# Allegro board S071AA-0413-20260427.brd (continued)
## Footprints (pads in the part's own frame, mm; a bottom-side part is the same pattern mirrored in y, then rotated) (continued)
SO8_215X127MM
  rect 1.778x0.762 smd: 1(-2.731,2.032) 4(-2.731,-2.032) 5(2.731,-2.032) 8(2.731,2.032)
  rect 1.778x0.61 smd: 2(-2.731,0.635) 3(-2.731,-0.635) 6(2.731,-0.635) 7(2.731,0.635)
SOCKET_CODE
  round 0.051 smd: 1(0,0)
TP_040_T
  round 1.016 smd: 1(0,0)
TP_060_040
  round 1.524 hole 1.016: 1(0,0)
V93K_TOUCHSENSOR_FY
  round 0.051 smd: 1(0,0)

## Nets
AGND: BDB4.1 BDB5.1 BDB6.1 BDB7.1 BDB8.1 BDB9.1 BDB10.1 BDB13.1 BDB14.1 BDB15.1 BDB16.1 BDB17.1 BDB18.1 BDB19.1 BDB20.1 BDB21.1 BDB22.1 BDB23.1 BDB24.1 BDB25.1 BDB26.1 BDB27.1 BDB28.1 BDB29.1 BDB30.1 BDB31.1 BDB32.1 BDB33.1 BDB34.1 BDB35.1 BDB36.1 BDB37.1 BDB38.1 BDB39.1 BDB40.1 BDB41.1 BDB42.1 BDB43.1 BDB44.1 BDB45.1 C1.2 C3.2 C4.2 C5.2 C6.2 C7.2 C8.2 C9.2 C20.2 C21.2 C22.2 C23.2 C24.2 C25.2 C26.2 C27.2 C28.2 C29.2 C30.2 C31.2 C32.2 C33.2 C34.2 C35.2 C36.2 C37.2 C38.2 C39.2 C40.2 C41.2 C42.2 C43.2 C44.2 C45.2 C46.2 C47.2 C48.2 C49.2 C74.2 C75.2 C76.2 C77.2 C78.2 C79.2 C80.2 C81.2 C82.2 C83.2 C84.2 C85.2 CSDPS225.B2 CSDPS225.B4 CSDPS225.B6 CSDPS225.B8 CSDPS225.B10 CSDPS225.B12 CSDPS225.B14 CSDPS225.B16 CSDPS225.C1 CSDPS225.C3 CSDPS225.C5 CSDPS225.C7 CSDPS225.C9 CSDPS225.C11 CSDPS225.C13 CSDPS225.C15 CSDPS226.B2 CSDPS226.B4 CSDPS226.B6 CSDPS226.B8 CSDPS226.B10 CSDPS226.B12 CSDPS226.B14 CSDPS226.B16 CSDPS226.C1 CSDPS226.C3 CSDPS226.C5 CSDPS226.C7 CSDPS226.C9 CSDPS226.C11 CSDPS226.C13 CSDPS226.C15 CSDPS229.B2 CSDPS229.B4 CSDPS229.B6 CSDPS229.B8 CSDPS229.B10 CSDPS229.B12 CSDPS229.B14 CSDPS229.B16 CSDPS229.C1 CSDPS229.C3 CSDPS229.C5 CSDPS229.C7 CSDPS229.C9 CSDPS229.C11 CSDPS229.C13 CSDPS229.C15 CSDPS425.B2 CSDPS425.B4 CSDPS425.B6 CSDPS425.B8 CSDPS425.B10 CSDPS425.B12 CSDPS425.B14 CSDPS425.B16 CSDPS425.C1 CSDPS425.C3 CSDPS425.C5 CSDPS425.C7 CSDPS425.C9 CSDPS425.C11 CSDPS425.C13 CSDPS425.C15 CSDPS426.B2 CSDPS426.B4 CSDPS426.B6 CSDPS426.B8 CSDPS426.B10 CSDPS426.B12 CSDPS426.B14 CSDPS426.B16 CSDPS426.C1 CSDPS426.C3 CSDPS426.C5 CSDPS426.C7 CSDPS426.C9 CSDPS426.C11 CSDPS426.C13 CSDPS426.C15 CSDPS429.B2 CSDPS429.B4 CSDPS429.B6 CSDPS429.B8 CSDPS429.B10 CSDPS429.B12 CSDPS429.B14 CSDPS429.B16 CSDPS429.C1 CSDPS429.C3 CSDPS429.C5 CSDPS429.C7 CSDPS429.C9 CSDPS429.C11 CSDPS429.C13 CSDPS429.C15 D101.A1 D101.A2 D101.A3 D101.A4 D101.A5 D101.A6 D101.A7 D101.A8 D101.A9 D101.A10 D101.A11 D101.A12 D101.A13 D101.A14 D101.A15 D101.A16 D101.B1 D101.B2 D101.B3 D101.B4 D101.B5 D101.B6 D101.B7 D101.B8 D101.B9 D101.B10 D101.B11 D101.B12 D101.B13 D101.B14 D101.B15 D101.B16 D102.A1 D102.A2 D102.A3 D102.A4 D102.A5 D102.A6 D102.A7 D102.A8 D102.A9 D102.A10 D102.A11 D102.A12 D102.A13 D102.A14 D102.A15 D102.A16 D102.B1 D102.B2 D102.B3 D102.B4 D102.B5 D102.B6 D102.B7 D102.B8 D102.B9 D102.B10 D102.B11 D102.B12 D102.B13 D102.B14 D102.B15 D102.B16 D103.A1 D103.A2 D103.A3 D103.A4 D103.A5 D103.A6 D103.A7 D103.A8 D103.A9 D103.A10 D103.A11 D103.A12 D103.A13 D103.A14 D103.A15 D103.A16 D103.B1 D103.B2 D103.B3 D103.B4 D103.B5 D103.B6 D103.B7 D103.B8 D103.B9 D103.B10 D103.B11 D103.B12 D103.B13 D103.B14 D103.B15 D103.B16 D104.A1 D104.A2 D104.A3 D104.A4 D104.A5 D104.A6 D104.A7 D104.A8 D104.A9 D104.A10 D104.A11 D104.A12 D104.A13 D104.A14 D104.A15 D104.A16 D104.B1 D104.B2 D104.B3 D104.B4 D104.B5 D104.B6 D104.B7 D104.B8 D104.B9 D104.B10 D104.B11 D104.B12 D104.B13 D104.B14 D104.B15 D104.B16 D105.A1 D105.A2 D105.A3 D105.A4 D105.A5 D105.A6 D105.A7 D105.A8 D105.A9 D105.A10 D105.A11 D105.A12 D105.A13 D105.A14 D105.A15 D105.A16 D105.B1 D105.B2 D105.B3 D105.B4 D105.B5 D105.B6 D105.B7 D105.B8 D105.B9 D105.B10 D105.B11 D105.B12 D105.B13 D105.B14 D105.B15 D105.B16 D106.A1 D106.A2 D106.A3 D106.A4 D106.A5 D106.A6 D106.A7 D106.A8 D106.A9 D106.A10 D106.A11 D106.A12 D106.A13 D106.A14 D106.A15 D106.A16 D106.B1 D106.B2 D106.B3 D106.B4 D106.B5 D106.B6 D106.B7 D106.B8 D106.B9 D106.B10 D106.B11 D106.B12 D106.B13 D106.B14 D106.B15 D106.B16 D107.A1 D107.A2 D107.A3 D107.A4 D107.A5 D107.A6 D107.A7 D107.A8 D107.A9 D107.A10 D107.A11 D107.A12 D107.A13 D107.A14 D107.A15 D107.A16 D107.B1 D107.B2 D107.B3 D107.B4 D107.B5 D107.B6 D107.B7 D107.B8 D107.B9 D107.B10 D107.B11 D107.B12 D107.B13 D107.B14 D107.B15 D107.B16 D108.A1 D108.A2 D108.A3 D108.A4 D108.A5 D108.A6 D108.A7 D108.A8 D108.A9 D108.A10 D108.A11 D108.A12 D108.A13 D108.A14 D108.A15 D108.A16 D108.B1 D108.B2 D108.B3 D108.B4 D108.B5 D108.B6 D108.B7 D108.B8 D108.B9 D108.B10 D108.B11 D108.B12 D108.B13 D108.B14 D108.B15 D108.B16 D109.A1 D109.A2 D109.A3 D109.A4 D109.A5 D109.A6 D109.A7 D109.A8 D109.A9 D109.A10 D109.A11 D109.A12 D109.A13 D109.A14 D109.A15 D109.A16 D109.B1 D109.B2 D109.B3 D109.B4 D109.B5 D109.B6 D109.B7 D109.B8 D109.B9 D109.B10 D109.B11 D109.B12 D109.B13 D109.B14 D109.B15 D109.B16 D110.A1 D110.A2 D110.A3 D110.A4 D110.A5 D110.A6 D110.A7 D110.A8 D110.A9 D110.A10 D110.A11 D110.A12 D110.A13 D110.A14 D110.A15 D110.A16 D110.B1 D110.B2 D110.B3 D110.B4 D110.B5 D110.B6 D110.B7 D110.B8 D110.B9 D110.B10 D110.B11 D110.B12 D110.B13 D110.B14 D110.B15 D110.B16 D111.A1 D111.A2 D111.A3 D111.A4 D111.A5 D111.A6 D111.A7 D111.A8 D111.A9 D111.A10 D111.A11 D111.A12 D111.A13 D111.A14 D111.A15 D111.A16 D111.B1 D111.B2 D111.B3 D111.B4 D111.B5 D111.B6 D111.B7 D111.B8 D111.B9 D111.B10 D111.B11 D111.B12 D111.B13 D111.B14 D111.B15 D111.B16 D112.A1 D112.A2 D112.A3 D112.A4 D112.A5 D112.A6 D112.A7 D112.A8 D112.A9 D112.A10 D112.A11 D112.A12 D112.A13 D112.A14 D112.A15 D112.A16 D112.B1 D112.B2 D112.B3 D112.B4 D112.B5 D112.B6 D112.B7 D112.B8 D112.B9 D112.B10 D112.B11 D112.B12 D112.B13 D112.B14 D112.B15 D112.B16 D113.A1 D113.A2 D113.A3 D113.A4 D113.A5 D113.A6 D113.A7 D113.A8 D113.A9 D113.A10 D113.A11 D113.A12 D113.A13 D113.A14 D113.A15 D113.A16 D113.B1 D113.B2 D113.B3 D113.B4 D113.B5 D113.B6 D113.B7 D113.B8 D113.B9 D113.B10 D113.B11 D113.B12 D113.B13 D113.B14 D113.B15 D113.B16 D114.A1 D114.A2 D114.A3 D114.A4 D114.A5 D114.A6 D114.A7 D114.A8 D114.A9 D114.A10 D114.A11 D114.A12 D114.A13 D114.A14 D114.A15 D114.A16 D114.B1 D114.B2 D114.B3 D114.B4 D114.B5 D114.B6 D114.B7 D114.B8 D114.B9 D114.B10 D114.B11 D114.B12 D114.B13 D114.B14 D114.B15 D114.B16 D115.A1 D115.A2 D115.A3 D115.A4 D115.A5 D115.A6 D115.A7 D115.A8 D115.A9 D115.A10 D115.A11 D115.A12 D115.A13 D115.A14 D115.A15 D115.A16 D115.B1 D115.B2 D115.B3 D115.B4 D115.B5 D115.B6 D115.B7 D115.B8 D115.B9 D115.B10 D115.B11 D115.B12 D115.B13 D115.B14 D115.B15 D115.B16 D116.A1 D116.A2 D116.A3 D116.A4 D116.A5 D116.A6 D116.A7 D116.A8 D116.A9 D116.A10 D116.A11 D116.A12 D116.A13 D116.A14 D116.A15 D116.A16 D116.B1 D116.B2 D116.B3 D116.B4 D116.B5 D116.B6 D116.B7 D116.B8 D116.B9 D116.B10 D116.B11 D116.B12 D116.B13 D116.B14 D116.B15 D116.B16 D117.A1 D117.A2 D117.A3 D117.A4 D117.A5 D117.A6 D117.A7 D117.A8 D117.A9 D117.A10 D117.A11 D117.A12 D117.A13 D117.A14 D117.A15 D117.A16 D117.B1 D117.B2 D117.B3 D117.B4 D117.B5 D117.B6 D117.B7 D117.B8 D117.B9 D117.B10 D117.B11 D117.B12 D117.B13 D117.B14 D117.B15 D117.B16 D118.A1 D118.A2 D118.A3 D118.A4 D118.A5 D118.A6 D118.A7 D118.A8 D118.A9 D118.A10 D118.A11 D118.A12 D118.A13 D118.A14 D118.A15 D118.A16 D118.B1 D118.B2 D118.B3 D118.B4 D118.B5 D118.B6 D118.B7 D118.B8 D118.B9 D118.B10 D118.B11 D118.B12 D118.B13 D118.B14 D118.B15 D118.B16 D119.A1 D119.A2 D119.A3 D119.A4 D119.A5 D119.A6 D119.A7 D119.A8 D119.A9 D119.A10 D119.A11 D119.A12 D119.A13 D119.A14 D119.A15 D119.A16 D119.B1 D119.B2 D119.B3 D119.B4 D119.B5 D119.B6 D119.B7 D119.B8 D119.B9 D119.B10 D119.B11 D119.B12 D119.B13 D119.B14 D119.B15 D119.B16 D120.A1 D120.A2 D120.A3 D120.A4 D120.A5 D120.A6 D120.A7 D120.A8 D120.A9 D120.A10 D120.A11 D120.A12 D120.A13 D120.A14 D120.A15 D120.A16 D120.B1 D120.B2 D120.B3 D120.B4 D120.B5 D120.B6 D120.B7 D120.B8 D120.B9 D120.B10 D120.B11 D120.B12 D120.B13 D120.B14 D120.B15 D120.B16 D121.A1 D121.A2 D121.A3 D121.A4 D121.A5 D121.A6 D121.A7 D121.A8 D121.A9 D121.A10 D121.A11 D121.A12 D121.A13 D121.A14 D121.A15 D121.A16 D121.B1 D121.B2 D121.B3 D121.B4 D121.B5 D121.B6 D121.B7 D121.B8 D121.B9 D121.B10 D121.B11 D121.B12 D121.B13 D121.B14 D121.B15 D121.B16 D122.A1 D122.A2 D122.A3 D122.A4 D122.A5 D122.A6 D122.A7 D122.A8 D122.A9 D122.A10 D122.A11 D122.A12 D122.A13 D122.A14 D122.A15 D122.A16 D122.B1 D122.B2 D122.B3 D122.B4 D122.B5 D122.B6 D122.B7 D122.B8 D122.B9 D122.B10 D122.B11 D122.B12 D122.B13 D122.B14 D122.B15 D122.B16 D123.A1 D123.A2 D123.A3 D123.A4 D123.A5 D123.A6 D123.A7 D123.A8 D123.A9 D123.A10 D123.A11 D123.A12 D123.A13 D123.A14 D123.A15 D123.A16 D123.B1 D123.B2 D123.B3 D123.B4 D123.B5 D123.B6 D123.B7 D123.B8 D123.B9 D123.B10 D123.B11 D123.B12 D123.B13 D123.B14 D123.B15 D123.B16 D124.A1 D124.A2 D124.A3 D124.A4 D124.A5 D124.A6 D124.A7 D124.A8 D124.A9 D124.A10 D124.A11 D124.A12 D124.A13 D124.A14 D124.A15 D124.A16 D124.B1 D124.B2 D124.B3 D124.B4 D124.B5 D124.B6 D124.B7 D124.B8 D124.B9 D124.B10 D124.B11 D124.B12 D124.B13 D124.B14 D124.B15 D124.B16 D227.A1 D227.A2 D227.A3 D227.A4 D227.A5 D227.A6 D227.A7 D227.A8 D227.A9 D227.A10 D227.A11 D227.A12 D227.A13 D227.A14 D227.A15 D227.A16 D227.A17 D227.B1 D227.B2 D227.B3 D227.B4 D227.B5 D227.B6 D227.B7 D227.B8 D227.B9 D227.B10 D227.B11 D227.B12 D227.B13 D227.B14 D227.B15 D227.B16 D227.B17 D228.A1 D228.A2 D228.A3 D228.A4 D228.A5 D228.A6 D228.A7 D228.A8 D228.A9 D228.A10 D228.A11 D228.A12 D228.A13 D228.A14 D228.A15 D228.A16 D228.A17 D228.B1 D228.B2 D228.B3 D228.B4 D228.B5 D228.B6 D228.B7 D228.B8 D228.B9 D228.B10 D228.B11 D228.B12 D228.B13 D228.B14 D228.B15 D228.B16 D228.B17 D231.A1 D231.A2 D231.A3 D231.A4 D231.A5 D231.A6 D231.A7 D231.A8 D231.A9 D231.A10 D231.A11 D231.A12 D231.A13 D231.A14 D231.A15 D231.A16 D231.A17 D231.B1 D231.B2 D231.B3 D231.B4 D231.B5 D231.B6 D231.B7 D231.B8 D231.B9 D231.B10 D231.B11 D231.B12 D231.B13 D231.B14 D231.B15 D231.B16 D231.B17 D232.A1 D232.A2 D232.A3 D232.A4 D232.A5 D232.A6 D232.A7 D232.A8 D232.A9 D232.A10 D232.A11 D232.A12 D232.A13 D232.A14 D232.A15 D232.A16 D232.A17 D232.B1 D232.B2 D232.B3 D232.B4 D232.B5 D232.B6 D232.B7 D232.B8 D232.B9 D232.B10 D232.B11 D232.B12 D232.B13 D232.B14 D232.B15 D232.B16 D232.B17 D427.A1 D427.A2 D427.A3 D427.A4 D427.A5 D427.A6 D427.A7 D427.A8 D427.A9 D427.A10 D427.A11 D427.A12 D427.A13 D427.A14 D427.A15 D427.A16 D427.A17 D427.B1 D427.B2 D427.B3 D427.B4 D427.B5 D427.B6 D427.B7 D427.B8 D427.B9 D427.B10 D427.B11 D427.B12 D427.B13 D427.B14 D427.B15 D427.B16 D427.B17 D428.A1 D428.A2 D428.A3 D428.A4 D428.A5 D428.A6 D428.A7 D428.A8 D428.A9 D428.A10 D428.A11 D428.A12 D428.A13 D428.A14 D428.A15 D428.A16 D428.A17 D428.B1 D428.B2 D428.B3 D428.B4 D428.B5 D428.B6 D428.B7 D428.B8 D428.B9 D428.B10 D428.B11 D428.B12 D428.B13 D428.B14 D428.B15 D428.B16 D428.B17 D431.A1 D431.A2 D431.A3 D431.A4 D431.A5 D431.A6 D431.A7 D431.A8 D431.A9 D431.A10 D431.A11 D431.A12 D431.A13 D431.A14 D431.A15 D431.A16 D431.A17 D431.B1 D431.B2 D431.B3 D431.B4 D431.B5 D431.B6 D431.B7 D431.B8 D431.B9 D431.B10 D431.B11 D431.B12 D431.B13 D431.B14 D431.B15 D431.B16 D431.B17 D432.A1 D432.A2 D432.A3 D432.A4 D432.A5 D432.A6 D432.A7 D432.A8 D432.A9 D432.A10 D432.A11 D432.A12 D432.A13 D432.A14 D432.A15 D432.A16 D432.A17 D432.B1 D432.B2 D432.B3 D432.B4 D432.B5 D432.B6 D432.B7 D432.B8 D432.B9 D432.B10 D432.B11 D432.B12 D432.B13 D432.B14 D432.B15 D432.B16 D432.B17 DPS1.A01 DPS1.A05 DPS1.A11 DPS1.A15 DPS1.B01 DPS1.B05 DPS1.B11 DPS1.B15 DPS1.C01 DPS1.C05 DPS1.C11 DPS1.C15 DPS2.A01 DPS2.A05 DPS2.A11 DPS2.A15 DPS2.B01 DPS2.B05 DPS2.B11 DPS2.B15 DPS2.C01 DPS2.C05 DPS2.C11 DPS2.C15 DPS3.A01 DPS3.A05 DPS3.A11 DPS3.A15 DPS3.B01 DPS3.B05 DPS3.B11 DPS3.B15 DPS3.C01 DPS3.C05 DPS3.C11 DPS3.C15 DPS8.A01 DPS8.A05 DPS8.A11 DPS8.A15 DPS8.B01 DPS8.B05 DPS8.B11 DPS8.B15 DPS8.C01 DPS8.C05 DPS8.C11 DPS8.C15 KS3.6(GND2) KS3.7(GND1) KS4.6(GND2) KS4.7(GND1) OSC1.2(GND) SB1.1 SB13.1 SB14.1 SB15.1 SH4.1 SH14.1 SH16.1 SITE1.E5(GNDK[1]) SITE1.E6(GNDK[2]) SITE1.E9(GNDK[3]) SITE1.E13(GNDK[4]) SITE1.E14(GNDK[5]) SITE1.F16(GNDK[6]) SITE1.G16(GNDK[7]) SITE1.H5(GNDK[8]) SITE1.H10(GNDK[9]) SITE1.H11(GNDK[10]) SITE1.J5(GNDK[11]) SITE1.J10(GNDK[12]) SITE1.J11(GNDK[13]) SITE1.K8(GNDK[14]) SITE1.K9(GNDK[15]) SITE1.K10(GNDK[16]) SITE1.K11(GNDK[17]) SITE1.K12(GNDK[18]) SITE1.K13(GNDK[19]) SITE1.L8(GNDK[20]) SITE1.L9(GNDK[21]) SITE1.L10(GNDK[22]) SITE1.L11(GNDK[23]) SITE1.L12(GNDK[24]) SITE1.M3(GNDK[25]) SITE1.M4(GNDK[26]) SITE1.M5(GNDK[27]) SITE1.M10(GNDK[28]) SITE1.M11(GNDK[29]) SITE1.T11(GND3IO_OSC) SITE1.T15(GNDK[30]) UHC230.G3 UHC230.G3_1 UHC230.G3_2 UHC230.G3_3 UHC230.G3_4 UHC230.G3_5 UHC230.G3_6 UHC230.G3_7 UHC230.G3_8 UHC230.G3_9 UHC230.G3_10 UHC230.G3_11 UHC230.G3_12 UHC230.G3_13 UHC230.G4 UHC230.G4_1 UHC230.G4_2 UHC230.G4_3 UHC230.G4_4 UHC230.G4_5 UHC230.G4_6 UHC230.G4_7 UHC230.G4_8 UHC230.G4_9 UHC230.G4_10 UHC230.G4_11 UHC230.G4_12 UHC230.G4_13 UHC430.G1 UHC430.G1_1 UHC430.G1_2 UHC430.G1_3 UHC430.G1_4 UHC430.G1_5 UHC430.G1_6 UHC430.G1_7 UHC430.G1_8 UHC430.G1_9 UHC430.G1_10 UHC430.G1_11 UHC430.G1_12 UHC430.G1_13 UHC430.G2 UHC430.G2_1 UHC430.G2_2 UHC430.G2_3 UHC430.G2_4 UHC430.G2_5 UHC430.G2_6 UHC430.G2_7 UHC430.G2_8 UHC430.G2_9 UHC430.G2_10 UHC430.G2_11 UHC430.G2_12 UHC430.G2_13
GND12A_SCG: BDB5.2 BDB6.2 BDB7.2 BDB8.2 BDB38.2 BDB39.2 BDB40.2 BDB41.2 C10.2 C50.2 C51.2 C52.2 C53.2 C54.2 C55.2 SH6.1 SITE1.T14(GND12A_SCG)
GND33A_ADC12: BDB9.2 BDB10.2 BDB17.2 BDB18.2 BDB34.2 BDB35.2 BDB36.2 BDB37.2 C11.2 C12.2 C13.2 C14.2 C56.2 C57.2 C58.2 C59.2 C60.2 C61.2 K33.6(GND2) K33.7(GND1) K34.6(GND2) K34.7(GND1) K35.6(GND2) K35.7(GND1) K36.6(GND2) K36.7(GND1) K37.6(GND2) K37.7(GND1) K38.6(GND2) K38.7(GND1) K39.6(GND2) K39.7(GND1) K40.6(GND2) K40.7(GND1) K41.6(GND2) K41.7(GND1) K42.6(GND2) K42.7(GND1) K43.6(GND2) K43.7(GND1) K44.6(GND2) K44.7(GND1) SH8.1 SITE1.N11(GND33D_ADC12) SITE1.T7(GND33A_ADC12[1]) SITE1.T10(XVRB_ADC12) SITE1.U10(GND33A_ADC12[2]) SITE1.V10(GND33A_ADC12[3]) SITE1.W6(GND33A_ADC12[4]) SITE1.W10(GND33A_ADC12[5]) SITE1.Y6(GND33A_ADC12[6]) SITE1.Y10(GND33A_ADC12[7])
GND33A_ADC32: BDB13.2 BDB14.2 BDB15.2 BDB16.2 BDB30.2 BDB31.2 BDB32.2 BDB33.2 C15.2 C16.2 C17.2 C18.2 C62.2 C63.2 C64.2 C65.2 C66.2 C67.2 K1.6(GND2) K1.7(GND1) K2.6(GND2) K2.7(GND1) K3.6(GND2) K3.7(GND1) K4.6(GND2) K4.7(GND1) K5.6(GND2) K5.7(GND1) K6.6(GND2) K6.7(GND1) K7.6(GND2) K7.7(GND1) K8.6(GND2) K8.7(GND1) K9.6(GND2) K9.7(GND1) K10.6(GND2) K10.7(GND1) K11.6(GND2) K11.7(GND1) K12.6(GND2) K12.7(GND1) K13.6(GND2) K13.7(GND1) K14.6(GND2) K14.7(GND1) K15.6(GND2) K15.7(GND1) K16.6(GND2) K16.7(GND1) K17.6(GND2) K17.7(GND1) K18.6(GND2) K18.7(GND1) K19.6(GND2) K19.7(GND1) K20.6(GND2) K20.7(GND1) K21.6(GND2) K21.7(GND1) K22.6(GND2) K22.7(GND1) K23.6(GND2) K23.7(GND1) K24.6(GND2) K24.7(GND1) K25.6(GND2) K25.7(GND1) K26.6(GND2) K26.7(GND1) K27.6(GND2) K27.7(GND1) K28.6(GND2) K28.7(GND1) K29.6(GND2) K29.7(GND1) K30.6(GND2) K30.7(GND1) K31.6(GND2) K31.7(GND1) K32.6(GND2) K32.7(GND1) SH10.1 SITE1.N1(GND33A_ADC32[1]) SITE1.N2(GND33A_ADC32[2]) SITE1.N3(GND33A_ADC32[3]) SITE1.N4(GND33A_ADC32[4]) SITE1.N5(GND33A_ADC32[5]) SITE1.N10(GND33D_ADC32) SITE1.P5(GND33A_ADC32[6]) SITE1.T6(XVRB_ADC32) SITE1.U6(GND33A_ADC32[7]) SITE1.V6(GND33A_ADC32[8])
GNDA_REG: BDB22.2 BDB23.2 BDB24.2 BDB25.2 BDB26.2 BDB27.2 BDB28.2 BDB29.2 C2.2 C19.2 C68.2 C69.2 C70.2 C71.2 C72.2 C73.2 SH12.1 SITE1.L13(GNDA_REG)
CSDPS225GS1: CSDPS225.D2
CSDPS225GS2: CSDPS225.A1
CSDPS225GS3: CSDPS225.D4
CSDPS225GS4: CSDPS225.A3
CSDPS225GS5: CSDPS225.D6
CSDPS225GS6: CSDPS225.A5
CSDPS225GS7: CSDPS225.D8
CSDPS225GS8: CSDPS225.A7
CSDPS225GS9: CSDPS225.D10
CSDPS225GS10: CSDPS225.A9
CSDPS225GS11: CSDPS225.D12
CSDPS225GS12: CSDPS225.A11
CSDPS225GS13: CSDPS225.D14
CSDPS225GS14: CSDPS225.A13
CSDPS225GS15: CSDPS225.D16
CSDPS225GS16: CSDPS225.A15
CSDPS225P1: CSDPS225.B1
CSDPS225P2: CSDPS225.C2
CSDPS225P3: CSDPS225.B3
CSDPS225P4: CSDPS225.C4
CSDPS225P5: CSDPS225.B5
CSDPS225P6: CSDPS225.C6
CSDPS225P7: CSDPS225.B7
CSDPS225P8: CSDPS225.C8
CSDPS225P9: CSDPS225.B9
CSDPS225P10: CSDPS225.C10
CSDPS225P11: CSDPS225.B11
CSDPS225P12: CSDPS225.C12
CSDPS225P13: CSDPS225.B13
CSDPS225P14: CSDPS225.C14
CSDPS225P15: CSDPS225.B15
CSDPS225P16: CSDPS225.C16
CSDPS225PS1: CSDPS225.D1
CSDPS225PS2: CSDPS225.A2
CSDPS225PS3: CSDPS225.D3
CSDPS225PS4: CSDPS225.A4
CSDPS225PS5: CSDPS225.D5
CSDPS225PS6: CSDPS225.A6
CSDPS225PS7: CSDPS225.D7
CSDPS225PS8: CSDPS225.A8
CSDPS225PS9: CSDPS225.D9
CSDPS225PS10: CSDPS225.A10
CSDPS225PS11: CSDPS225.D11
CSDPS225PS12: CSDPS225.A12
CSDPS225PS13: CSDPS225.D13
CSDPS225PS14: CSDPS225.A14
CSDPS225PS15: CSDPS225.D15
CSDPS225PS16: CSDPS225.A16
CSDPS226GS1: CSDPS226.D2
CSDPS226GS2: CSDPS226.A1
CSDPS226GS3: CSDPS226.D4
CSDPS226GS4: CSDPS226.A3
CSDPS226GS5: CSDPS226.D6
CSDPS226GS6: CSDPS226.A5
CSDPS226GS7: CSDPS226.D8
CSDPS226GS8: CSDPS226.A7
CSDPS226GS9: CSDPS226.D10
CSDPS226GS10: CSDPS226.A9
CSDPS226GS11: CSDPS226.D12
CSDPS226GS12: CSDPS226.A11
CSDPS226GS13: CSDPS226.D14
CSDPS226GS14: CSDPS226.A13
CSDPS226GS15: CSDPS226.D16
CSDPS226GS16: CSDPS226.A15
CSDPS226P1: CSDPS226.B1
CSDPS226P2: CSDPS226.C2
CSDPS226P3: CSDPS226.B3
CSDPS226P4: CSDPS226.C4
CSDPS226P5: CSDPS226.B5
CSDPS226P6: CSDPS226.C6
CSDPS226P7: CSDPS226.B7
CSDPS226P8: CSDPS226.C8
CSDPS226P9: CSDPS226.B9
CSDPS226P10: CSDPS226.C10
CSDPS226P11: CSDPS226.B11
CSDPS226P12: CSDPS226.C12
CSDPS226P13: CSDPS226.B13
CSDPS226P14: CSDPS226.C14
CSDPS226P15: CSDPS226.B15
CSDPS226P16: CSDPS226.C16
CSDPS226PS1: CSDPS226.D1
CSDPS226PS2: CSDPS226.A2
CSDPS226PS3: CSDPS226.D3
CSDPS226PS4: CSDPS226.A4
CSDPS226PS5: CSDPS226.D5
CSDPS226PS6: CSDPS226.A6
CSDPS226PS7: CSDPS226.D7
CSDPS226PS8: CSDPS226.A8
CSDPS226PS9: CSDPS226.D9
CSDPS226PS10: CSDPS226.A10
CSDPS226PS11: CSDPS226.D11
CSDPS226PS12: CSDPS226.A12
CSDPS226PS13: CSDPS226.D13
CSDPS226PS14: CSDPS226.A14
CSDPS226PS15: CSDPS226.D15
CSDPS226PS16: CSDPS226.A16
CSDPS226WW: CSDPS226.B17
CSDPS226XX: CSDPS226.C17
CSDPS229GS1: CSDPS229.D2
CSDPS229GS2: CSDPS229.A1
CSDPS229GS3: CSDPS229.D4
CSDPS229GS4: CSDPS229.A3
CSDPS229GS5: CSDPS229.D6
CSDPS229GS6: CSDPS229.A5
CSDPS229GS7: CSDPS229.D8
CSDPS229GS8: CSDPS229.A7
CSDPS229GS9: CSDPS229.D10
CSDPS229GS10: CSDPS229.A9
CSDPS229GS11: CSDPS229.D12
CSDPS229GS12: CSDPS229.A11
CSDPS229GS13: CSDPS229.D14
CSDPS229GS14: CSDPS229.A13
CSDPS229GS15: CSDPS229.D16
CSDPS229GS16: CSDPS229.A15
CSDPS229P1: CSDPS229.B1
CSDPS229P2: CSDPS229.C2
CSDPS229P3: CSDPS229.B3
CSDPS229P4: CSDPS229.C4
CSDPS229P5: CSDPS229.B5
CSDPS229P6: CSDPS229.C6
CSDPS229P7: CSDPS229.B7
CSDPS229P8: CSDPS229.C8
CSDPS229P9: CSDPS229.B9
CSDPS229P10: CSDPS229.C10
CSDPS229P11: CSDPS229.B11
CSDPS229P12: CSDPS229.C12
CSDPS229P13: CSDPS229.B13
CSDPS229P14: CSDPS229.C14
CSDPS229P15: CSDPS229.B15
CSDPS229P16: CSDPS229.C16
CSDPS229PS1: CSDPS229.D1
CSDPS229PS2: CSDPS229.A2
CSDPS229PS3: CSDPS229.D3
CSDPS229PS4: CSDPS229.A4
CSDPS229PS5: CSDPS229.D5
CSDPS229PS6: CSDPS229.A6
CSDPS229PS7: CSDPS229.D7
CSDPS229PS8: CSDPS229.A8
CSDPS229PS9: CSDPS229.D9
CSDPS229PS10: CSDPS229.A10
CSDPS229PS11: CSDPS229.D11
CSDPS229PS12: CSDPS229.A12
CSDPS229PS13: CSDPS229.D13
CSDPS229PS14: CSDPS229.A14
CSDPS229PS15: CSDPS229.D15
CSDPS229PS16: CSDPS229.A16
CSDPS425GS1: CSDPS425.D2
CSDPS425GS2: CSDPS425.A1
CSDPS425GS3: CSDPS425.D4
CSDPS425GS4: CSDPS425.A3
CSDPS425GS5: CSDPS425.D6
CSDPS425GS6: CSDPS425.A5
CSDPS425GS7: CSDPS425.D8
CSDPS425GS8: CSDPS425.A7
CSDPS425GS9: CSDPS425.D10
CSDPS425GS10: CSDPS425.A9
CSDPS425GS11: CSDPS425.D12
CSDPS425GS12: CSDPS425.A11
CSDPS425GS13: CSDPS425.D14
CSDPS425GS14: CSDPS425.A13
CSDPS425GS15: CSDPS425.D16
CSDPS425GS16: CSDPS425.A15
CSDPS425P1: CSDPS425.B1
CSDPS425P2: CSDPS425.C2
CSDPS425P3: CSDPS425.B3
CSDPS425P4: CSDPS425.C4
CSDPS425P5: CSDPS425.B5
CSDPS425P6: CSDPS425.C6
CSDPS425P7: CSDPS425.B7
CSDPS425P8: CSDPS425.C8
CSDPS425P9: CSDPS425.B9
CSDPS425P10: CSDPS425.C10
CSDPS425P11: CSDPS425.B11
CSDPS425P12: CSDPS425.C12
CSDPS425P13: CSDPS425.B13
CSDPS425P14: CSDPS425.C14
CSDPS425P15: CSDPS425.B15
CSDPS425P16: CSDPS425.C16
CSDPS425PS1: CSDPS425.D1
CSDPS425PS2: CSDPS425.A2
CSDPS425PS3: CSDPS425.D3
CSDPS425PS4: CSDPS425.A4
CSDPS425PS5: CSDPS425.D5
CSDPS425PS6: CSDPS425.A6
CSDPS425PS7: CSDPS425.D7
CSDPS425PS8: CSDPS425.A8
CSDPS425PS9: CSDPS425.D9
CSDPS425PS10: CSDPS425.A10
CSDPS425PS11: CSDPS425.D11
CSDPS425PS12: CSDPS425.A12
CSDPS425PS13: CSDPS425.D13
CSDPS425PS14: CSDPS425.A14
CSDPS425PS15: CSDPS425.D15
CSDPS425PS16: CSDPS425.A16
CSDPS426GS1: CSDPS426.D2
CSDPS426GS2: CSDPS426.A1
CSDPS426GS3: CSDPS426.D4
CSDPS426GS4: CSDPS426.A3
CSDPS426GS5: CSDPS426.D6
CSDPS426GS6: CSDPS426.A5
CSDPS426GS7: CSDPS426.D8
CSDPS426GS8: CSDPS426.A7
CSDPS426GS9: CSDPS426.D10
CSDPS426GS10: CSDPS426.A9
CSDPS426GS11: CSDPS426.D12
CSDPS426GS12: CSDPS426.A11
CSDPS426GS13: CSDPS426.D14
CSDPS426GS14: CSDPS426.A13
CSDPS426GS15: CSDPS426.D16
CSDPS426GS16: CSDPS426.A15
CSDPS426P1: CSDPS426.B1
CSDPS426P2: CSDPS426.C2
CSDPS426P3: CSDPS426.B3
CSDPS426P4: CSDPS426.C4
CSDPS426P5: CSDPS426.B5
CSDPS426P6: CSDPS426.C6
CSDPS426P7: CSDPS426.B7
CSDPS426P8: CSDPS426.C8
CSDPS426P9: CSDPS426.B9
CSDPS426P10: CSDPS426.C10
CSDPS426P11: CSDPS426.B11
CSDPS426P12: CSDPS426.C12
CSDPS426P13: CSDPS426.B13
CSDPS426P14: CSDPS426.C14
CSDPS426P15: CSDPS426.B15
CSDPS426P16: CSDPS426.C16
CSDPS426PS1: CSDPS426.D1
CSDPS426PS2: CSDPS426.A2
CSDPS426PS3: CSDPS426.D3
CSDPS426PS4: CSDPS426.A4
CSDPS426PS5: CSDPS426.D5
CSDPS426PS6: CSDPS426.A6
CSDPS426PS7: CSDPS426.D7
CSDPS426PS8: CSDPS426.A8
CSDPS426PS9: CSDPS426.D9
CSDPS426PS10: CSDPS426.A10
CSDPS426PS11: CSDPS426.D11
CSDPS426PS12: CSDPS426.A12
CSDPS426PS13: CSDPS426.D13
CSDPS426PS14: CSDPS426.A14
CSDPS426PS15: CSDPS426.D15
CSDPS426PS16: CSDPS426.A16
CSDPS426WW: CSDPS426.B17
CSDPS426XX: CSDPS426.C17
CSDPS429GS1: CSDPS429.D2
CSDPS429GS2: CSDPS429.A1
CSDPS429GS3: CSDPS429.D4
CSDPS429GS4: CSDPS429.A3
CSDPS429GS5: CSDPS429.D6
CSDPS429GS6: CSDPS429.A5
CSDPS429GS7: CSDPS429.D8
CSDPS429GS8: CSDPS429.A7
CSDPS429GS9: CSDPS429.D10
CSDPS429GS10: CSDPS429.A9
CSDPS429GS11: CSDPS429.D12
CSDPS429GS12: CSDPS429.A11
CSDPS429GS13: CSDPS429.D14
CSDPS429GS14: CSDPS429.A13
CSDPS429GS15: CSDPS429.D16
CSDPS429GS16: CSDPS429.A15
CSDPS429P1: CSDPS429.B1
CSDPS429P2: CSDPS429.C2
CSDPS429P3: CSDPS429.B3
CSDPS429P4: CSDPS429.C4
CSDPS429P5: CSDPS429.B5
CSDPS429P6: CSDPS429.C6
CSDPS429P7: CSDPS429.B7
CSDPS429P8: CSDPS429.C8
CSDPS429P9: CSDPS429.B9
CSDPS429P10: CSDPS429.C10
CSDPS429P11: CSDPS429.B11
CSDPS429P12: CSDPS429.C12
CSDPS429P13: CSDPS429.B13
CSDPS429P14: CSDPS429.C14
CSDPS429P15: CSDPS429.B15
CSDPS429P16: CSDPS429.C16
CSDPS429PS1: CSDPS429.D1
CSDPS429PS2: CSDPS429.A2
CSDPS429PS3: CSDPS429.D3
CSDPS429PS4: CSDPS429.A4
CSDPS429PS5: CSDPS429.D5
CSDPS429PS6: CSDPS429.A6
CSDPS429PS7: CSDPS429.D7
CSDPS429PS8: CSDPS429.A8
CSDPS429PS9: CSDPS429.D9
CSDPS429PS10: CSDPS429.A10
CSDPS429PS11: CSDPS429.D11
CSDPS429PS12: CSDPS429.A12
CSDPS429PS13: CSDPS429.D13
CSDPS429PS14: CSDPS429.A14
CSDPS429PS15: CSDPS429.D15
CSDPS429PS16: CSDPS429.A16
D227_4_TRIG: D227.04
D228_4_TRIG: D228.04
D231_MCB1_CT2: D231.17 TR3.1
D231_MCB1_E+: D231.16
D231_MCB1_E-: D231.15
D231_MCB1_EE+: D231.08
D231_MCB1_EE-: D231.07
D231_MCB1_F+: D231.14
D231_MCB1_F-: D231.13
D231_MCB1_FF+: D231.06
D231_MCB1_FF-: D231.05
D231_MCB1_G+: D231.12
D231_MCB1_G-: D231.11
D231_MCB1_GG+: D231.04
D231_MCB1_GG-: D231.03
D231_MCB1_H+: D231.10
D231_MCB1_H-: D231.09
D231_MCB1_HH+: D231.02
D231_MCB1_HH-: D231.01
D232_4_TRIG: D232.04
D232_MCB1_CT2: D232.17
D232_MCB1_E+: D232.16
D232_MCB1_E-: D232.15
D232_MCB1_EE+: D232.08
D232_MCB1_EE-: D232.07
D232_MCB1_F+: D232.14
D232_MCB1_F-: D232.13
D232_MCB1_FF+: D232.06
D232_MCB1_FF-: D232.05
D232_MCB1_G+: D232.12
D232_MCB1_G-: D232.11
D232_MCB1_GG-: D232.03
D232_MCB1_H+: D232.10
D232_MCB1_H-: D232.09
D232_MCB1_HH+: D232.02
D232_MCB1_HH-: D232.01
D431_MCB1_A+: D431.16 K1.5 K2.5 K3.5 K4.5 K5.5 K6.5 K7.5 K8.5 K9.5 K10.5 K11.5 K12.5 K13.5 K14.5 K15.5 K16.5
D431_MCB1_A-: D431.15 K17.5 K18.5 K19.5 K20.5 K21.5 K22.5 K23.5 K24.5 K25.5 K26.5 K27.5 K28.5 K29.5 K30.5 K31.5 K32.5
D431_MCB1_AA+: D431.08
D431_MCB1_AA-: D431.07
D431_MCB1_B+: D431.14
D431_MCB1_B-: D431.13
D431_MCB1_BB+: D431.06
D431_MCB1_BB-: D431.05
D431_MCB1_C+: D431.12 K33.5 K34.5 K35.5 K36.5 K37.5 K38.5
D431_MCB1_C-: D431.11 K39.5 K40.5 K41.5 K42.5 K43.5 K44.5
D431_MCB1_CC+: D431.04
D431_MCB1_CC-: D431.03
D431_MCB1_CT1: D431.17 TR2.1
D431_MCB1_D+: D431.10
D431_MCB1_D-: D431.09
D431_MCB1_DD+: D431.02
D431_MCB1_DD-: D431.01
D432_MCB1_A+: D432.16
D432_MCB1_A-: D432.15
D432_MCB1_AA+: D432.08
D432_MCB1_AA-: D432.07
D432_MCB1_B+: D432.14
D432_MCB1_B-: D432.13
D432_MCB1_BB+: D432.06
D432_MCB1_BB-: D432.05
D432_MCB1_C+: D432.12
D432_MCB1_C-: D432.11
D432_MCB1_CC+: D432.04
D432_MCB1_CC-: D432.03
D432_MCB1_CT1: D432.17
D432_MCB1_D+: D432.10
D432_MCB1_D-: D432.09
D432_MCB1_DD+: D432.02
D432_MCB1_DD-: D432.01
D10101: D101.01
D10102: D101.02
D10103: D101.03
D10104: D101.04
D10105: D101.05
D10106: D101.06
D10107: D101.07
D10108: D101.08
D10109: D101.09
D10110: D101.10
D10111: D101.11
D10112: D101.12
D10113: D101.13
D10114: D101.14
D10115: D101.15
D10116: D101.16
D10201: D102.01
D10202: D102.02
D10203: D102.03
D10204: D102.04
D10205: D102.05
D10206: D102.06
D10207: D102.07
D10208: D102.08
D10209: D102.09
D10210: D102.10
D10211: D102.11
D10212: D102.12
D10213: D102.13
D10214: D102.14
D10215: D102.15
D10216: D102.16
D10301: D103.01
D10302: D103.02
D10303: D103.03
D10304: D103.04
D10305: D103.05
D10306: D103.06
D10307: D103.07
D10308: D103.08
D10309: D103.09
D10310: D103.10
D10311: D103.11
D10312: D103.12
D10313: D103.13
D10314: D103.14
D10315: D103.15
D10316: D103.16
D10401: D104.01
D10402: D104.02
D10403: D104.03
D10404: D104.04
D10405: D104.05
D10406: D104.06
D10407: D104.07
D10408: D104.08
D10409: D104.09
D10410: D104.10
D10411: D104.11
D10412: D104.12
D10413: D104.13
D10414: D104.14
D10415: D104.15
D10416: D104.16
D10501: D105.01
D10502: D105.02
D10503: D105.03
D10504: D105.04
D10505: D105.05
D10506: D105.06
D10507: D105.07
D10508: D105.08
D10509: D105.09
D10510: D105.10
D10511: D105.11
D10512: D105.12
D10513: D105.13
D10514: D105.14
D10515: D105.15
D10516: D105.16
D10601: D106.01
D10602: D106.02
D10603: D106.03
D10604: D106.04
D10605: D106.05
D10606: D106.06
D10607: D106.07
D10608: D106.08
D10609: D106.09
D10610: D106.10
D10611: D106.11
D10612: D106.12
D10613: D106.13
D10614: D106.14
D10615: D106.15
D10616: D106.16
D10701: D107.01
D10702: D107.02
D10703: D107.03
D10704: D107.04
D10705: D107.05
D10706: D107.06
D10707: D107.07
D10708: D107.08
D10709: D107.09
D10710: D107.10
D10711: D107.11
D10712: D107.12
D10713: D107.13
D10714: D107.14
D10715: D107.15
D10716: D107.16
D10801: D108.01
D10802: D108.02
D10803: D108.03
D10804: D108.04
D10805: D108.05
D10806: D108.06
D10807: D108.07
D10808: D108.08
D10809: D108.09
D10810: D108.10
D10811: D108.11
D10812: D108.12
D10813: D108.13
D10814: D108.14
D10815: D108.15
D10816: D108.16
D10901: D109.01
D10902: D109.02
D10903: D109.03
D10904: D109.04
D10905: D109.05
D10906: D109.06
D10907: D109.07
D10908: D109.08
D10909: D109.09
D10910: D109.10
D10911: D109.11
D10912: D109.12
D10913: D109.13
D10914: D109.14
D10915: D109.15
D10916: D109.16
D11001: D110.01
D11002: D110.02
D11003: D110.03
D11004: D110.04
D11005: D110.05
D11006: D110.06
D11007: D110.07
D11008: D110.08
D11009: D110.09
D11010: D110.10
D11011: D110.11
D11012: D110.12
D11013: D110.13
D11014: D110.14
D11015: D110.15
D11016: D110.16
D11101: D111.01
D11102: D111.02
D11103: D111.03
D11104: D111.04
D11105: D111.05
D11106: D111.06
D11107: D111.07
D11108: D111.08
D11109: D111.09
D11110: D111.10
D11111: D111.11
D11112: D111.12
D11113: D111.13
D11114: D111.14
D11115: D111.15
D11116: D111.16
D11201: D112.01
D11202: D112.02
D11203: D112.03
D11204: D112.04
D11205: D112.05
D11206: D112.06
D11207: D112.07
D11208: D112.08
D11209: D112.09
D11210: D112.10
D11211: D112.11
D11212: D112.12
D11213: D112.13
D11214: D112.14
D11215: D112.15
D11216: D112.16
D11301: D113.01
D11302: D113.02
D11303: D113.03
D11304: D113.04
D11305: D113.05
D11306: D113.06
D11307: D113.07
D11308: D113.08
D11309: D113.09
D11310: D113.10
D11311: D113.11
D11312: D113.12
D11313: D113.13
D11314: D113.14
D11315: D113.15
D11316: D113.16
D11401: D114.01
D11402: D114.02
D11403: D114.03
D11404: D114.04
D11405: D114.05
D11406: D114.06
D11407: D114.07
D11408: D114.08
D11409: D114.09
D11410: D114.10
D11411: D114.11
D11412: D114.12
D11413: D114.13
D11414: D114.14
D11415: D114.15
D11416: D114.16
D11501: D115.01
D11502: D115.02
D11503: D115.03
D11504: D115.04
D11505: D115.05
D11506: D115.06
D11507: D115.07
D11508: D115.08
D11509: D115.09
D11510: D115.10
D11511: D115.11
D11512: D115.12
D11513: D115.13
D11514: D115.14
D11515: D115.15
D11516: D115.16
D11601: D116.01
D11602: D116.02
D11603: D116.03
D11604: D116.04
D11605: D116.05
D11606: D116.06
D11607: D116.07
D11608: D116.08
D11609: D116.09
D11610: D116.10
D11611: D116.11
D11612: D116.12
D11613: D116.13
D11614: D116.14
D11615: D116.15
D11616: D116.16 TR2.2 TR3.2
D11701: D117.01
D11702: D117.02
D11703: D117.03
D11704: D117.04
D11705: D117.05
D11706: D117.06
D11707: D117.07
D11708: D117.08
D11709: D117.09
D11710: D117.10
D11711: D117.11
D11712: D117.12
D11713: D117.13
D11714: D117.14
D11715: D117.15
D11716: D117.16
D11801: D118.01
D11802: D118.02
D11803: D118.03
D11804: D118.04
D11805: D118.05
D11806: D118.06
D11807: D118.07
D11808: D118.08
D11809: D118.09
D11810: D118.10
D11811: D118.11
D11812: D118.12
D11813: D118.13
D11814: D118.14
D11815: D118.15
D11816: D118.16
D11901: D119.01
D11902: D119.02
D11903: D119.03
D11904: D119.04
D11905: D119.05
D11906: D119.06
D11907: D119.07
D11908: D119.08
D11909: D119.09
D11910: D119.10
D11911: D119.11
D11912: D119.12
D11913: D119.13
D11914: D119.14
D11915: D119.15
D11916: D119.16
D12001: D120.01
D12002: D120.02
D12003: D120.03
D12004: D120.04
D12005: D120.05
D12006: D120.06
D12007: D120.07
D12008: D120.08
D12009: D120.09
D12010: D120.10
D12011: D120.11
D12012: D120.12
D12013: D120.13
D12014: D120.14
D12015: D120.15
D12016: D120.16
D12101: D121.01
D12102: D121.02
D12103: D121.03
D12104: D121.04
D12105: D121.05
D12106: D121.06
D12107: D121.07
D12108: D121.08
D12109: D121.09
D12110: D121.10
D12111: D121.11
D12112: D121.12
D12113: D121.13
D12114: D121.14
D12115: D121.15
D12116: D121.16
D12201: D122.01
D12202: D122.02
D12203: D122.03
D12204: D122.04
D12205: D122.05
D12206: D122.06
D12207: D122.07
D12208: D122.08
D12209: D122.09
D12210: D122.10
D12211: D122.11
D12212: D122.12
D12213: D122.13
D12214: D122.14
D12215: D122.15
D12216: D122.16
D12301: D123.01
D12302: D123.02
D12303: D123.03
D12304: D123.04
D12305: D123.05
D12306: D123.06
D12307: D123.07
D12308: D123.08
D12309: D123.09
D12310: D123.10
D12311: D123.11
D12312: D123.12
D12313: D123.13
D12314: D123.14
D12315: D123.15
D12316: D123.16
D12401: D124.01
D12402: D124.02
D12403: D124.03
D12404: D124.04
D12405: D124.05
D12406: D124.06
D12407: D124.07
D12408: D124.08
D12409: D124.09
D12410: D124.10
D12411: D124.11
D12412: D124.12
D12413: D124.13
D12414: D124.14
D12415: D124.15
D12416: D124.16
GPDPS1_1F: DPS1.A03 DPS1.B03 DPS1.C03 R162.2
GPDPS1_1GRD: DPS1.B02
GPDPS1_1GS: DPS1.A02 R163.2
GPDPS1_1S: DPS1.C02 R160.2
GPDPS1_2F: DPS1.A07 DPS1.B07 DPS1.C07 R155.2
GPDPS1_2GRD: DPS1.B06
GPDPS1_2GS: DPS1.A06 R157.2
GPDPS1_2S: DPS1.C06 R154.2
GPDPS1_3F: DPS1.A13 DPS1.B13 DPS1.C13 R143.2
GPDPS1_3GRD: DPS1.B12
GPDPS1_3GS: DPS1.A12 R145.2
GPDPS1_3S: DPS1.C12 R142.2
GPDPS1_4F: DPS1.A17 DPS1.B17 DPS1.C17 R137.2
GPDPS1_4GRD: DPS1.B16
GPDPS1_4GS: DPS1.A16 R139.2
GPDPS1_4S: DPS1.C16 R136.2
GPDPS1_TR+: DPS1.A09
GPDPS1_TRVB-: DPS1.B09 SB1.2
GPDPS1_VB+: DPS1.C09
GPDPS2_1F: DPS2.A03 DPS2.B03 DPS2.C03 R132.2
GPDPS2_1GRD: DPS2.B02
GPDPS2_1GS: DPS2.A02 R133.2
GPDPS2_1S: DPS2.C02 R130.2
GPDPS2_2F: DPS2.A07 DPS2.B07 DPS2.C07 R149.2
GPDPS2_2GRD: DPS2.B06
GPDPS2_2GS: DPS2.A06 R151.2
GPDPS2_2S: DPS2.C06 R148.2
GPDPS2_3F: DPS2.A13 DPS2.B13 DPS2.C13 R125.2
GPDPS2_3GRD: DPS2.B12
GPDPS2_3GS: DPS2.A12 R127.2
GPDPS2_3S: DPS2.C12 R124.2
GPDPS2_4F: DPS2.A17 DPS2.B17 DPS2.C17
GPDPS2_4GRD: DPS2.B16
GPDPS2_4GS: DPS2.A16
GPDPS2_4S: DPS2.C16
GPDPS2_TR+: DPS2.A09
GPDPS2_TRVB-: DPS2.B09 SB13.2
GPDPS2_VB+: DPS2.C09
GPDPS3_1F: DPS3.A03 DPS3.B03 DPS3.C03
GPDPS3_1GRD: DPS3.B02
GPDPS3_1GS: DPS3.A02
GPDPS3_1S: DPS3.C02
GPDPS3_2F: DPS3.A07 DPS3.B07 DPS3.C07
GPDPS3_2GRD: DPS3.B06
GPDPS3_2GS: DPS3.A06
GPDPS3_2S: DPS3.C06
GPDPS3_3F: DPS3.A13 DPS3.B13 DPS3.C13
GPDPS3_3GRD: DPS3.B12
GPDPS3_3GS: DPS3.A12
GPDPS3_3S: DPS3.C12
GPDPS3_4F: DPS3.A17 DPS3.B17 DPS3.C17
GPDPS3_4GRD: DPS3.B16
GPDPS3_4GS: DPS3.A16
GPDPS3_4S: DPS3.C16
GPDPS3_TR+: DPS3.A09
GPDPS3_TRVB-: DPS3.B09 SB14.2
GPDPS3_VB+: DPS3.C09
GPDPS8_1F: DPS8.A03 DPS8.B03 DPS8.C03
GPDPS8_1GRD: DPS8.B02
GPDPS8_1GS: DPS8.A02
GPDPS8_1S: DPS8.C02
GPDPS8_2F: DPS8.A07 DPS8.B07 DPS8.C07
GPDPS8_2GRD: DPS8.B06
GPDPS8_2GS: DPS8.A06
GPDPS8_2S: DPS8.C06
GPDPS8_3F: DPS8.A13 DPS8.B13 DPS8.C13
GPDPS8_3GRD: DPS8.B12
GPDPS8_3GS: DPS8.A12
GPDPS8_3S: DPS8.C12
GPDPS8_4F: DPS8.A17 DPS8.B17 DPS8.C17
GPDPS8_4GRD: DPS8.B16
GPDPS8_4GS: DPS8.A16
GPDPS8_4S: DPS8.C16
GPDPS8_TR+: DPS8.A09
GPDPS8_TRVB-: DPS8.B09 SB15.2
GPDPS8_VB+: DPS8.C09
S1_ADC1_VIN[0]: K1.8 SITE1.Y5(ADC1_VIN[0])
S1_ADC1_VIN[1]: K2.8 SITE1.W5(ADC1_VIN[1])
S1_ADC1_VIN[2]: K3.8 SITE1.V5(ADC1_VIN[2])
S1_ADC1_VIN[3]: K4.8 SITE1.V4(ADC1_VIN[3])
S1_ADC1_VIN[4]: K5.8 SITE1.W4(ADC1_VIN[4])
S1_ADC1_VIN[5]: K6.8 SITE1.Y4(ADC1_VIN[5])
S1_ADC1_VIN[6]: K7.8 SITE1.V3(ADC1_VIN[6])
S1_ADC1_VIN[7]: K8.8 SITE1.W3(ADC1_VIN[7])
S1_ADC1_VIN[8]: K9.8 SITE1.Y3(ADC1_VIN[8])
S1_ADC1_VIN[9]: K10.8 SITE1.Y2(ADC1_VIN[9])
S1_ADC1_VIN[10]: K11.8 SITE1.Y1(ADC1_VIN[10])
S1_ADC1_VIN[11]: K12.8 SITE1.W2(ADC1_VIN[11])
S1_ADC1_VIN[12]: K13.8 SITE1.W1(ADC1_VIN[12])
S1_ADC1_VIN[13]: K14.8 SITE1.V2(ADC1_VIN[13])
S1_ADC1_VIN[14]: K15.8 SITE1.V1(ADC1_VIN[14])
S1_ADC1_VIN[15]: K16.8 SITE1.U5(ADC1_VIN[15])
S1_ADC1_VIN[16]: K17.8 SITE1.U4(ADC1_VIN[16])
S1_ADC1_VIN[17]: K18.8 SITE1.U3(ADC1_VIN[17])
S1_ADC1_VIN[18]: K19.8 SITE1.U2(ADC1_VIN[18])
S1_ADC1_VIN[19]: K20.8 SITE1.U1(ADC1_VIN[19])
S1_ADC1_VIN[20]: K21.8 SITE1.T4(ADC1_VIN[20])
S1_ADC1_VIN[21]: K22.8 SITE1.T3(ADC1_VIN[21])
S1_ADC1_VIN[22]: K23.8 SITE1.T2(ADC1_VIN[22])
S1_ADC1_VIN[23]: K24.8 SITE1.T1(ADC1_VIN[23])
S1_ADC1_VIN[24]: K25.8 SITE1.R4(ADC1_VIN[24])
S1_ADC1_VIN[25]: K26.8 SITE1.R3(ADC1_VIN[25])
S1_ADC1_VIN[26]: K27.8 SITE1.R2(ADC1_VIN[26])
S1_ADC1_VIN[27]: K28.8 SITE1.R1(ADC1_VIN[27])
S1_ADC1_VIN[28]: K29.8 SITE1.P4(ADC1_VIN[28])
S1_ADC1_VIN[29]: K30.8 SITE1.P3(ADC1_VIN[29])
S1_ADC1_VIN[30]: K31.8 SITE1.P2(ADC1_VIN[30])
S1_ADC1_VIN[31]: K32.8 SITE1.P1(ADC1_VIN[31])
S1_ADC2_VIN[0]: K33.8 SITE1.Y7(ADC2_VIN[0])
S1_ADC2_VIN[1]: K34.8 SITE1.W7(ADC2_VIN[1])
S1_ADC2_VIN[2]: K35.8 SITE1.V7(ADC2_VIN[2])
S1_ADC2_VIN[3]: K36.8 SITE1.U7(ADC2_VIN[3])
S1_ADC2_VIN[4]: K37.8 SITE1.Y8(ADC2_VIN[4])
S1_ADC2_VIN[5]: K38.8 SITE1.W8(ADC2_VIN[5])
S1_ADC2_VIN[6]: K39.8 SITE1.V8(ADC2_VIN[6])
S1_ADC2_VIN[7]: K40.8 SITE1.U8(ADC2_VIN[7])
S1_ADC2_VIN[8]: K41.8 SITE1.Y9(ADC2_VIN[8])
S1_ADC2_VIN[9]: K42.8 SITE1.W9(ADC2_VIN[9])
S1_ADC2_VIN[10]: K43.8 SITE1.V9(ADC2_VIN[10])
S1_ADC2_VIN[11]: K44.8 SITE1.U9(ADC2_VIN[11])
S1_CBIT001: K1.1(V-) LD1.2(B)
S1_CBIT002: K2.1(V-) LD2.2(B)
S1_CBIT003: K3.1(V-) LD3.2(B)
S1_CBIT004: K4.1(V-) LD4.2(B)
S1_CBIT005: K5.1(V-) LD5.2(B)
S1_CBIT006: K6.1(V-) LD6.2(B)
S1_CBIT007: K7.1(V-) LD7.2(B)
S1_CBIT008: K8.1(V-) LD8.2(B)
S1_CBIT009: K9.1(V-) LD9.2(B)
S1_CBIT010: K10.1(V-) LD10.2(B)
S1_CBIT011: K11.1(V-) LD11.2(B)
S1_CBIT012: K12.1(V-) LD12.2(B)
S1_CBIT013: K13.1(V-) LD13.2(B)
S1_CBIT014: K14.1(V-) LD14.2(B)
S1_CBIT015: K15.1(V-) LD15.2(B)
S1_CBIT016: K16.1(V-) LD16.2(B)
S1_CBIT017: K17.1(V-) LD17.2(B)
S1_CBIT018: K18.1(V-) LD18.2(B)
S1_CBIT019: K19.1(V-) LD19.2(B)
S1_CBIT020: K20.1(V-) LD20.2(B)
S1_CBIT021: K21.1(V-) LD21.2(B)
S1_CBIT022: K22.1(V-) LD22.2(B)
S1_CBIT023: K23.1(V-) LD23.2(B)
S1_CBIT024: K24.1(V-) LD24.2(B)
S1_CBIT025: K25.1(V-) LD25.2(B)
S1_CBIT026: K26.1(V-) LD26.2(B)
S1_CBIT027: K27.1(V-) LD27.2(B)
S1_CBIT028: K28.1(V-) LD28.2(B)
S1_CBIT029: K29.1(V-) LD29.2(B)
S1_CBIT030: K30.1(V-) LD30.2(B)
S1_CBIT031: K31.1(V-) LD31.2(B)
S1_CBIT032: K32.1(V-) LD32.2(B)
S1_CBIT033: K33.1(V-) LD33.2(B)
S1_CBIT034: K34.1(V-) LD34.2(B)
S1_CBIT035: K35.1(V-) LD35.2(B)
S1_CBIT036: K36.1(V-) LD36.2(B)
S1_CBIT037: K37.1(V-) LD37.2(B)
S1_CBIT038: K38.1(V-) LD38.2(B)
S1_CBIT039: K39.1(V-) LD39.2(B)
S1_CBIT040: K40.1(V-) LD40.2(B)
S1_CBIT041: K41.1(V-) LD41.2(B)
S1_CBIT042: K42.1(V-) LD42.2(B)
S1_CBIT043: K43.1(V-) LD43.2(B)
S1_CBIT044: K44.1(V-) LD44.2(B)
S1_CBIT045: K45.8(V-) LD45.2(B)
S1_CBIT046: K46.8(V-) LD46.2(B)
S1_CSDPS1-1F: R126.2
S1_CSDPS1-1GS: R128.2
S1_CSDPS1-1S: R123.2
S1_CSDPS2-1F: R131.2
S1_CSDPS2-1GS: R134.2
S1_CSDPS2-1S: R129.2
S1_CSDPS3-1F: R138.2
S1_CSDPS3-1GS: R140.2
S1_CSDPS3-1S: R135.2
S1_CSDPS4-1F: R144.2
S1_CSDPS4-1GS: R146.2
S1_CSDPS4-1S: R141.2
S1_CSDPS5-1F: R150.2
S1_CSDPS5-1GS: R152.2
S1_CSDPS5-1S: R147.2
S1_CSDPS6-1F: R156.2
S1_CSDPS6-1GS: R158.2
S1_CSDPS6-1S: R153.2
S1_CSDPS7-1F: R161.2
S1_CSDPS7-1GS: R164.2
S1_CSDPS7-1S: R159.2
S1_DCH001: K1.4
S1_DCH002: K2.4
S1_DCH003: K3.4
S1_DCH004: K4.4
S1_DCH005: K5.4
S1_DCH006: K6.4
S1_DCH007: K7.4
S1_DCH008: K8.4
S1_DCH009: K9.4
S1_DCH010: K10.4
S1_DCH011: K11.4
S1_DCH012: K12.4
S1_DCH013: K13.4
S1_DCH014: K14.4
S1_DCH015: K15.4
S1_DCH016: K16.4
S1_DCH017: K17.4
S1_DCH018: K18.4
S1_DCH019: K19.4
S1_DCH020: K20.4
S1_DCH021: K21.4
S1_DCH022: K22.4
S1_DCH023: K23.4
S1_DCH024: K24.4
S1_DCH025: K25.4
S1_DCH026: K26.4
S1_DCH027: K27.4
S1_DCH028: K28.4
S1_DCH029: K29.4
S1_DCH030: K30.4
S1_DCH031: K31.4
S1_DCH032: K32.4
S1_DCH033: K33.4
S1_DCH034: K34.4
S1_DCH035: K35.4
S1_DCH036: K36.4
S1_DCH037: K37.4
S1_DCH038: K38.4
S1_DCH039: K39.4
S1_DCH040: K40.4
S1_DCH041: K41.4
S1_DCH042: K42.4
S1_DCH043: K43.4
S1_DCH044: K44.4
S1_DCH045: SITE1.N20(PIO_A[0])
S1_DCH046: SITE1.P20(PIO_A[1])
S1_DCH047: SITE1.L18(PIO_A[2])
S1_DCH048: SITE1.R20(PIO_A[3])
S1_DCH049: SITE1.K18(PIO_A[4])
S1_DCH050: SITE1.N19(PIO_A[5])
S1_DCH051: SITE1.K17(PIO_A[6])
S1_DCH052: SITE1.P19(PIO_A[7])
S1_DCH053: SITE1.M17(PIO_B[0])
S1_DCH054: SITE1.T19(PIO_B[1])
S1_DCH055: SITE1.R17(PIO_B[2])
S1_DCH056: SITE1.U19(PIO_B[3])
S1_DCH057: SITE1.R18(PIO_B[4])
S1_DCH058: SITE1.U20(PIO_B[5])
S1_DCH059: SITE1.T18(PIO_B[6])
S1_DCH060: SITE1.V20(PIO_B[7])
S1_DCH061: SITE1.M18(PIO_C[0])
S1_DCH062: SITE1.L17(PIO_C[1])
S1_DCH063: SITE1.R19(PIO_C[2])
S1_DCH064: SITE1.T20(PIO_C[3])
S1_DCH065: SITE1.M19(PIO_C[4])
S1_DCH066: SITE1.M20(PIO_C[5])
S1_DCH067: SITE1.L19(PIO_C[6])
S1_DCH068: SITE1.L20(PIO_C[7])
S1_DCH069: SITE1.G20(PIO_D[0])
S1_DCH070: SITE1.H20(PIO_D[1])
S1_DCH071: SITE1.J20(PIO_D[2])
S1_DCH072: SITE1.K20(PIO_D[3])
S1_DCH073: SITE1.H19(PIO_D[4])
S1_DCH074: SITE1.J19(PIO_D[5])
S1_DCH075: SITE1.K19(PIO_D[6])
S1_DCH076: SITE1.H18(PIO_D[7])
S1_DCH077: SITE1.J18(PIO_E[0])
S1_DCH078: SITE1.H17(PIO_E[1])
S1_DCH079: SITE1.J17(PIO_E[2])
S1_DCH080: SITE1.M16(PIO_E[3])
S1_DCH081: SITE1.L16(PIO_E[4])
S1_DCH082: SITE1.K16(PIO_E[5])
S1_DCH083: SITE1.J16(PIO_E[6])
S1_DCH084: SITE1.H16(PIO_E[7])
S1_DCH085: SITE1.E2(PIO_F[0])
S1_DCH086: SITE1.F3(PIO_F[1])
S1_DCH087: SITE1.C1(PIO_F[2])
S1_DCH088: SITE1.D3(PIO_F[3])
S1_DCH089: SITE1.E4(PIO_F[4])
S1_DCH090: SITE1.A3(PIO_F[5])
S1_DCH091: SITE1.C3(PIO_F[6])
S1_DCH092: SITE1.D5(PIO_F[7])
S1_DCH093: SITE1.D1(PIO_G[0])
S1_DCH094: SITE1.D2(PIO_G[1])
S1_DCH095: SITE1.B1(PIO_G[2])
S1_DCH096: SITE1.E3(PIO_G[3])
S1_DCH097: SITE1.A2(PIO_G[4])
S1_DCH098: SITE1.B3(PIO_G[5])
S1_DCH099: SITE1.B4(PIO_G[6])
S1_DCH100: SITE1.H2(PIO_G[7])
S1_DCH101: SITE1.G4(PIO_H[0])
S1_DCH102: SITE1.F4(PIO_H[1])
S1_DCH103: SITE1.C2(PIO_H[2])
S1_DCH104: SITE1.A1(PIO_H[3])
S1_DCH105: SITE1.A4(PIO_H[4])
S1_DCH106: SITE1.C4(PIO_H[5])
S1_DCH107: SITE1.H1(PIO_H[6])
S1_DCH108: SITE1.G1(PIO_H[7])
S1_DCH109: SITE1.B2(PIO_I[0])
S1_DCH110: SITE1.D4(PIO_I[1])
S1_DCH111: SITE1.A5(PIO_I[2])
S1_DCH112: SITE1.J3(PIO_I[3])
S1_DCH113: SITE1.J4(PIO_I[4])
S1_DCH114: SITE1.G2(PIO_I[5])
S1_DCH115: SITE1.F1(PIO_I[6])
S1_DCH116: SITE1.H3(PIO_I[7])
S1_DCH117: SITE1.G3(PIO_J[0])
S1_DCH118: SITE1.H4(PIO_J[1])
S1_DCH119: SITE1.E1(PIO_J[2])
S1_DCH120: SITE1.F2(PIO_J[3])
S1_DCH121: SITE1.V13(PIO_J[4])
S1_DCH122: SITE1.Y14(PIO_J[5])
S1_DCH123: SITE1.U13(PIO_J[6])
S1_DCH124: SITE1.W14(PIO_J[7])
S1_DCH125: SITE1.U12(PIO_K[0])
S1_DCH126: SITE1.Y13(PIO_K[1])
S1_DCH127: SITE1.W13(PIO_K[2])
S1_DCH128: SITE1.U11(PIO_K[3])
S1_DCH129: SITE1.V11(PIO_K[4])
S1_DCH130: SITE1.W11(PIO_K[5])
S1_DCH131: SITE1.W12(PIO_K[6])
S1_DCH132: SITE1.V12(PIO_K[7])
S1_DCH133: SITE1.B7(PIO_L[0])
S1_DCH134: SITE1.A7(PIO_L[1])
S1_DCH135: SITE1.D8(PIO_L[2])
S1_DCH136: SITE1.C8(PIO_L[3])
S1_DCH137: SITE1.B8(PIO_L[4])
S1_DCH138: SITE1.A8(PIO_L[5])
S1_DCH139: SITE1.B9(PIO_L[6])
S1_DCH140: SITE1.A9(PIO_L[7])
S1_DCH141: SITE1.D7(PIO_M[0])
S1_DCH142: SITE1.C7(PIO_M[1])
S1_DCH143: SITE1.D6(PIO_M[2])
S1_DCH144: SITE1.C6(PIO_M[3])
S1_DCH145: SITE1.B6(PIO_M[4])
S1_DCH146: SITE1.A6(PIO_M[5])
S1_DCH147: SITE1.C5(PIO_M[6])
S1_DCH148: SITE1.B5(PIO_M[7])
S1_DCH149: SITE1.V14(PIO_N[0])
S1_DCH150: SITE1.U14(PIO_N[1])
S1_DCH151: SITE1.Y15(PIO_N[2])
S1_DCH152: SITE1.W15(PIO_N[3])
S1_DCH153: SITE1.V15(PIO_N[4])
S1_DCH154: SITE1.U15(PIO_N[5])
S1_DCH155: SITE1.Y16(PIO_N[6])
S1_DCH156: SITE1.W16(PIO_N[7])
S1_DCH157: SITE1.V16(PIO_O[0])
S1_DCH158: SITE1.U16(PIO_O[1])
S1_DCH159: SITE1.W17(PIO_O[2])
S1_DCH160: SITE1.Y17(PIO_O[3])
S1_DCH161: SITE1.Y18(PIO_O[4])
S1_DCH162: SITE1.Y19(PIO_O[5])
S1_DCH163: SITE1.V17(PIO_O[6])
S1_DCH164: SITE1.W18(PIO_O[7])
S1_DCH165: SITE1.T17(PIO_P[0])
S1_DCH166: SITE1.W20(PIO_P[1])
S1_DCH167: SITE1.W19(PIO_P[2])
S1_DCH168: SITE1.U17(PIO_P[3])
S1_DCH169: SITE1.U18(PIO_P[4])
S1_DCH170: SITE1.V19(PIO_P[5])
S1_DCH171: SITE1.Y20(PIO_P[6])
S1_DCH172: SITE1.V18(PIO_P[7])
S1_DCH173: SITE1.L4(PIO_Q[0])
S1_DCH174: SITE1.L3(PIO_Q[1])
S1_DCH175: SITE1.K4(PIO_Q[2])
S1_DCH176: SITE1.K3(PIO_Q[3])
S1_DCH177: SITE1.K2(PIO_Q[4])
S1_DCH178: SITE1.K1(PIO_Q[5])
S1_DCH179: SITE1.J2(PIO_Q[6])
S1_DCH180: SITE1.J1(PIO_Q[7])
S1_DCH181: SITE1.M1(PIO_R[0])
S1_DCH182: SITE1.M2(PIO_R[1])
S1_DCH183: SITE1.L1(PIO_R[2])
S1_DCH184: SITE1.L2(PIO_R[3])
S1_DCH185: SITE1.A17(PIO_R[4])
S1_DCH186: SITE1.C14(PIO_R[5])
S1_DCH187: SITE1.B13(PIO_R[6])
S1_DCH188: SITE1.A16(PIO_R[7])
S1_DCH189: SITE1.A10(PIO_S[0])
S1_DCH190: SITE1.B11(PIO_S[1])
S1_DCH191: SITE1.B10(PIO_S[2])
S1_DCH192: SITE1.C10(PIO_S[3])
S1_DCH193: SITE1.C9(PIO_S[4])
S1_DCH194: SITE1.D9(PIO_S[5])
S1_DCH195: SITE1.C15(PIO_T[0])
S1_DCH196: SITE1.D14(PIO_T[1])
S1_DCH197: SITE1.B15(PIO_T[2])
S1_DCH198: SITE1.A15(PIO_T[3])
S1_DCH199: SITE1.D13(PIO_T[4])
S1_DCH200: SITE1.D12(PIO_T[5])
S1_DCH201: SITE1.B14(PIO_T[6])
S1_DCH202: SITE1.A13(PIO_T[7])
S1_DCH203: SITE1.C13(PIO_U[0])
S1_DCH204: SITE1.A14(PIO_U[1])
S1_DCH205: SITE1.C16(PIO_U[2])
S1_DCH206: SITE1.A19(PIO_U[3])
S1_DCH207: SITE1.D17(PIO_U[4])
S1_DCH208: SITE1.D15(PIO_U[5])
S1_DCH209: SITE1.A18(PIO_U[6])
S1_DCH210: SITE1.B16(PIO_U[7])
S1_DCH211: SITE1.B17(PIO_V[0])
S1_DCH212: SITE1.C17(PIO_V[1])
S1_DCH213: SITE1.D18(PIO_V[2])
S1_DCH214: SITE1.C18(PIO_V[3])
S1_DCH215: SITE1.B18(PIO_V[4])
S1_DCH216: SITE1.A20(PIO_V[5])
S1_DCH217: SITE1.B19(PIO_V[6])
S1_DCH218: SITE1.B20(PIO_V[7])
S1_DCH219: SITE1.D16(PIO_W[0])
S1_DCH220: SITE1.C19(PIO_W[1])
S1_DCH221: SITE1.D19(PIO_W[2])
S1_DCH222: SITE1.E20(PIO_W[3])
S1_DCH223: SITE1.C20(PIO_W[4])
S1_DCH224: SITE1.D20(PIO_W[5])
S1_DCH225: SITE1.E18(PIO_W[6])
S1_DCH226: SITE1.E19(PIO_W[7])
S1_DCH227: SITE1.E17(PIO_X[0])
S1_DCH228: SITE1.F17(PIO_X[1])
S1_DCH229: SITE1.G17(PIO_X[2])
S1_DCH230: SITE1.G18(PIO_X[3])
S1_DCH231: SITE1.F18(PIO_X[4])
S1_DCH232: SITE1.G19(PIO_X[5])
S1_DCH233: SITE1.F19(PIO_X[6])
S1_DCH234: SITE1.F20(PIO_X[7])
S1_DCH235: SITE1.A11(RESET)
S1_DCH236: SITE1.C12(TCK)
S1_DCH237: SITE1.D11(TDI)
S1_DCH238: SITE1.C11(TDO)
S1_DCH239: SITE1.D10(TMS)
S1_DCH240: SITE1.B12(TRST)
S1_DCH241: SITE1.Y11(XIN)
S1_DCH242: SITE1.E11(BUS_SEL)
S1_DCH243: SITE1.E10(CLK_EN)
S1_DCH244: SITE1.A12(MODE_SELECT)
S1_DCH245: K45.2
S1_DCH246: K46.4 K46.5
S1_DPS11: C38.1 C39.1 C40.1 C41.1 C42.1 C43.1 C44.1 C45.1 C46.1 C47.1 C48.1 C49.1 C80.1 C81.1 C82.1 C83.1 C84.1 C85.1 R161.1 R162.1 SH15.1 SITE1.H8(VCCK[1]) SITE1.H9(VCCK[2]) SITE1.H12(VCCK[3]) SITE1.H13(VCCK[4]) SITE1.J8(VCCK[5]) SITE1.J9(VCCK[6]) SITE1.J12(VCCK[7]) SITE1.J13(VCCK[8]) SITE1.M8(VCCK[9]) SITE1.M9(VCCK[10]) SITE1.M12(VCCK[11]) SITE1.N8(VCCK[12]) TP_DPS11.1(TP)
S1_DPS12: C20.1 C21.1 C22.1 C23.1 C24.1 C25.1 C26.1 C27.1 C28.1 C29.1 C30.1 C31.1 C32.1 C33.1 C34.1 C35.1 C36.1 C37.1 C74.1 C75.1 C76.1 C77.1 C78.1 C79.1 R155.1 R156.1 SH13.1 SITE1.E7(VCC3IO[1]) SITE1.E8(VCC3IO[2]) SITE1.E12(VCC3IO[3]) SITE1.E15(VCC3IO[4]) SITE1.E16(VCC3IO[5]) SITE1.F5(VCC3IO[6]) SITE1.G5(VCC3IO[7]) SITE1.K5(VCC3IO[8]) SITE1.L5(VCC3IO[9]) SITE1.N16(VCC3IO[10]) SITE1.N17(VCC3IO[11]) SITE1.N18(VCC3IO[12]) SITE1.P16(VCC3IO[13]) SITE1.P17(VCC3IO[14]) SITE1.P18(VCC3IO[15]) SITE1.R16(VCC3IO[16]) SITE1.T12(VCC3IO_OSC) SITE1.T16(VCC3IO[17]) TP_DPS12.1(TP)
S1_DPS13: C15.1 C16.1 C17.1 C18.1 C62.1 C63.1 C64.1 C65.1 C66.1 C67.1 R143.1 R144.1 SH9.1 SITE1.N9(VCC33D_ADC32) SITE1.R5(VCC33A_ADC32) SITE1.T5(XVRT_ADC32) TP_DPS13.1(TP)
S1_DPS14: C11.1 C12.1 C13.1 C14.1 C56.1 C57.1 C58.1 C59.1 C60.1 C61.1 R137.1 R138.1 SH7.1 SITE1.N12(VCC33D_ADC12) SITE1.T8(VCC33A_ADC12) SITE1.T9(XVRT_ADC12) TP_DPS14.1(TP)
S1_DPS21: C10.1 C50.1 C51.1 C52.1 C53.1 C54.1 C55.1 R131.1 R132.1 SH5.1 SITE1.T13(VCC12A_SCG) TP_DPS21.1(TP)
S1_DPS22: C19.1 C68.1 C69.1 C70.1 C71.1 C72.1 C73.1 R149.1 R150.1 SH11.1 SITE1.M13(VCC33A_REG) TP_DPS22.1(TP)
S1_DPS23: C1.1 C3.1 C4.1 C5.1 C6.1 C7.1 C8.1 C9.1 OSC1.4(VDD) R125.1 R126.1 SH3.1 TP_DPS23.1(TP)
S1_VCC12A_O_REG: C2.1 K46.3 K46.6 SITE1.N13(VCC12A_O_REG)
S1_XOUT: K45.3 SITE1.Y12(XOUT)
UDBGND: BDB4.2 BDB19.2 BDB20.2 BDB21.2 BDB42.2 BDB43.2 BDB44.2 BDB45.2 CB1.2 CB2.2 CB3.2 CB4.2 CB5.2 CB6.2 CB7.2 CB8.2 LDB1.2(B) UB1.1(NC) UB1.2(A1/NC) UB1.3(A2) UB1.4(GND) UB1.7(WP) UHC230.B2(GND2) UHC230.D2(GND1) UHC430.B2(GND2) UHC430.D2(GND1) UTL1.A02 UTL1.A08 UTL1.A10 UTL1.A12 UTL1.A14 UTL1.B01 UTL1.B07 UTL1.B09 UTL1.B11 UTL1.B13 UTL2.A02 UTL2.A08 UTL2.A10 UTL2.A12 UTL2.A14 UTL2.B01 UTL2.B07 UTL2.B09 UTL2.B11 UTL2.B13 UTL3.A02 UTL3.A08 UTL3.A10 UTL3.A12 UTL3.A14 UTL3.B01 UTL3.B07 UTL3.B09 UTL3.B11 UTL3.B13 UTL4.A02 UTL4.A08 UTL4.A10 UTL4.A12 UTL4.A14 UTL4.B01 UTL4.B07 UTL4.B09 UTL4.B11 UTL4.B13 XC1.1
UHC230A_CMON3: UHC230.C2(CMON3)
UHC230A_CMON4: UHC230.A2(CMON4)
UHC230A_DS3+: UHC230.B1(+DS3)
UHC230A_DS3-: UHC230.A1(-DS3)
UHC230A_DS4+: UHC230.B3(+DS4)
UHC230A_DS4-: UHC230.A3(-DS4)
UHC230A_DUT_CAP_ON_3: UHC230.D4(DUT_CAP_ON_3)
UHC230A_DUT_CAP_ON_4: UHC230.A4(DUT_CAP_ON_4)
UHC230A_GANG_OUT: UHC230.B4(GANG_OUT)
UHC230A_GS3: UHC230.C1(GS3)
UHC230A_GS4: UHC230.C3(GS4)
UHC230A_P3: UHC230.P3 UHC230.P3_1 UHC230.P3_2 UHC230.P3_3 UHC230.P3_4 UHC230.P3_5 UHC230.P3_6 UHC230.P3_7 UHC230.P3_8 UHC230.P3_9 UHC230.P3_10 UHC230.P3_11 UHC230.P3_12 UHC230.P3_13 UHC230.P3_14 UHC230.P3_15 UHC230.P3_16 UHC230.P3_17 UHC230.P3_18
UHC230A_P4: UHC230.P4 UHC230.P4_1 UHC230.P4_2 UHC230.P4_3 UHC230.P4_4 UHC230.P4_5 UHC230.P4_6 UHC230.P4_7 UHC230.P4_8 UHC230.P4_9 UHC230.P4_10 UHC230.P4_11 UHC230.P4_12 UHC230.P4_13 UHC230.P4_14 UHC230.P4_15 UHC230.P4_16 UHC230.P4_17 UHC230.P4_18
UHC230A_PS3: UHC230.D1(PS3)
UHC230A_PS4: UHC230.D3(PS4)
UHC230A_SAFETY_LINE: UHC230.C4(SAFETY_LINE)
UHC430B_CMON1: UHC430.C2(CMON1)
UHC430B_CMON2: UHC430.A2(CMON2)
UHC430B_DS1+: UHC430.B1(+DS1)
UHC430B_DS1-: UHC430.A1(-DS1)
UHC430B_DS2+: UHC430.B3(+DS2)
UHC430B_DS2-: UHC430.A3(-DS2)
UHC430B_DUT_CAP_ON_1: UHC430.D4(DUT_CAP_ON_1)
UHC430B_DUT_CAP_ON_2: UHC430.A4(DUT_CAP_ON_2)
UHC430B_GANG_IN: UHC430.B4(GANG_IN)
UHC430B_GS1: UHC430.C1(GS1)
UHC430B_GS2: UHC430.C3(GS2)
UHC430B_P1: UHC430.P1 UHC430.P1_1 UHC430.P1_2 UHC430.P1_3 UHC430.P1_4 UHC430.P1_5 UHC430.P1_6 UHC430.P1_7 UHC430.P1_8 UHC430.P1_9 UHC430.P1_10 UHC430.P1_11 UHC430.P1_12 UHC430.P1_13 UHC430.P1_14 UHC430.P1_15 UHC430.P1_16 UHC430.P1_17 UHC430.P1_18
UHC430B_P2: UHC430.P2 UHC430.P2_1 UHC430.P2_2 UHC430.P2_3 UHC430.P2_4 UHC430.P2_5 UHC430.P2_6 UHC430.P2_7 UHC430.P2_8 UHC430.P2_9 UHC430.P2_10 UHC430.P2_11 UHC430.P2_12 UHC430.P2_13 UHC430.P2_14 UHC430.P2_15 UHC430.P2_16 UHC430.P2_17 UHC430.P2_18
UHC430B_PS1: UHC430.D1(PS1)
UHC430B_PS2: UHC430.D3(PS2)
UT1_PDCF: UTL1.B15
UT1_PDCS: UTL1.A15
UT1_PGDS: UTL1.A16
UT1_PGRD: UTL1.B16
UT1_UP5V: CB1.1 CB2.1 CB3.1 CB4.1 CB5.1 CB6.1 CB7.1 CB8.1 K1.3(V+) K2.3(V+) K3.3(V+) K4.3(V+) K5.3(V+) K6.3(V+) K7.3(V+) K8.3(V+) K9.3(V+) K10.3(V+) K11.3(V+) K12.3(V+) K13.3(V+) K14.3(V+) K15.3(V+) K16.3(V+) K17.3(V+) K18.3(V+) K19.3(V+) K20.3(V+) K21.3(V+) K22.3(V+) K23.3(V+) K24.3(V+) K25.3(V+) K26.3(V+) K27.3(V+) K28.3(V+) K29.3(V+) K30.3(V+) K31.3(V+) K32.3(V+) K33.3(V+) K34.3(V+) K35.3(V+) K36.3(V+) K37.3(V+) K38.3(V+) K39.3(V+) K40.3(V+) K41.3(V+) K42.3(V+) K43.3(V+) K44.3(V+) K45.1(V+) K46.1(V+) KS1.1(V+) KS2.1(V+) KS3.3(V+) KS4.3(V+) LRB1.2 LRB2.1 LRB3.1 LRB4.1 LRB5.1 R1.2 R2.2 R3.2 R4.2 R5.2 R6.2 R7.2 R8.2 R9.2 R10.2 R11.2 R12.2 R13.2 R14.2 R15.2 R16.2 R17.2 R18.2 R19.2 R20.2 R21.2 R22.2 R23.2 R24.2 R25.2 R26.2 R27.2 R28.2 R29.2 R30.2 R31.2 R32.2 R33.2 R34.2 R35.2 R36.2 R37.2 R38.2 R39.2 R40.2 R41.2 R42.2 R43.2 R44.2 R45.2 R46.2 RB1.1 RB2.1 UB1.8(VCC) UHC430.C4(+5V) UT_UP5V1.1(TP) UTL1.A05 UTL1.B04 UTL2.A05 UTL2.B04 UTL3.A05 UTL3.B04 UTL4.A05 UTL4.B04 XC1.2
UT1_URW00: KS1.9(V-) LDB2.2(B) UTL1.A01
UT1_URW01: KS2.9(V-) LDB3.2(B) UTL1.B02
UT1_URW02: KS3.1(V-) LDB4.2(B) UTL1.A03
UT1_URW03: KS4.1(V-) LDB5.2(B) UTL1.B03
UT1_URW04: UTL1.A04
UT1_URW05: UTL1.B05
UT1_URW06: UTL1.A06
UT1_UW07: UTL1.B06
UT1_UW08: UTL1.A07
UT1_UW09: UTL1.B08
UT1_UW10: UTL1.A09
UT1_UW11: UTL1.B10
UT1_UW12: UTL1.A11
UT1_UW13: UTL1.B12
UT1_UW14: RB1.2 UB1.6(SCL) UTL1.A13
UT1_UW15: RB2.2 UB1.5(SDA) UTL1.B14
UT2_PDCF: UTL2.B15
UT2_PDCS: UTL2.A15
UT2_PGDS: UTL2.A16
UT2_PGRD: UTL2.B16
UT2_URW00: UTL2.A01
UT2_URW01: UTL2.B02
UT2_URW02: UTL2.A03
UT2_URW03: UTL2.B03
UT2_URW04: UTL2.A04
UT2_URW05: UTL2.B05
UT2_URW06: UTL2.A06
UT2_UW07: UTL2.B06
UT2_UW08: UTL2.A07
UT2_UW09: UTL2.B08
UT2_UW10: UTL2.A09
UT2_UW11: UTL2.B10
UT2_UW12: UTL2.A11
UT2_UW13: UTL2.B12
UT2_UW14: UTL2.A13
UT2_UW15: UTL2.B14
UT3_PDCF: UTL3.B15
UT3_PDCS: UTL3.A15
UT3_PGDS: UTL3.A16
UT3_PGRD: UTL3.B16
UT3_URW00: UTL3.A01
UT3_URW01: UTL3.B02
UT3_URW02: UTL3.A03
UT3_URW03: UTL3.B03
UT3_URW04: UTL3.A04
UT3_URW05: UTL3.B05
UT3_URW06: UTL3.A06
UT3_UW07: UTL3.B06
UT3_UW08: UTL3.A07
UT3_UW09: UTL3.B08
UT3_UW10: UTL3.A09
UT3_UW11: UTL3.B10
UT3_UW12: UTL3.A11
UT3_UW13: UTL3.B12
UT3_UW14: UTL3.A13
UT3_UW15: UTL3.B14
UT4_PDCF: UTL4.B15
UT4_PDCS: UTL4.A15
UT4_PGDS: UTL4.A16
UT4_PGRD: UTL4.B16
UT4_URW00: UTL4.A01
UT4_URW01: UTL4.B02
UT4_URW02: UTL4.A03
UT4_URW03: UTL4.B03
UT4_URW04: UTL4.A04
UT4_URW05: UTL4.B05
UT4_URW06: UTL4.A06
UT4_UW07: UTL4.B06
